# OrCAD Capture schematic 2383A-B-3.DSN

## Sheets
1 PAGE3: size A
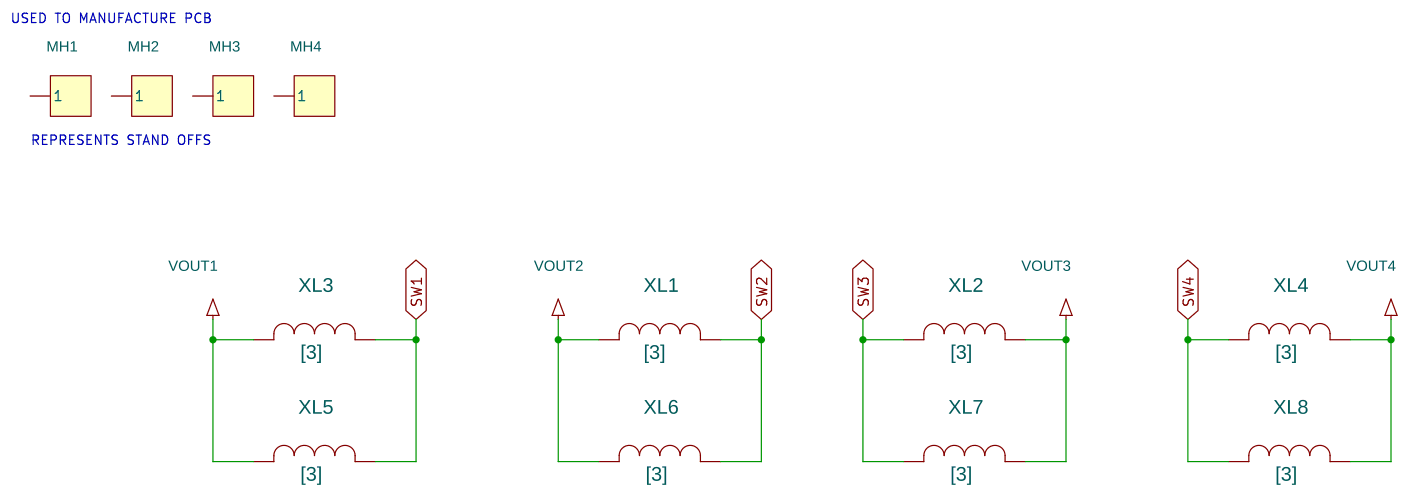
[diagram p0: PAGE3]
2 PAGE1: size Custom
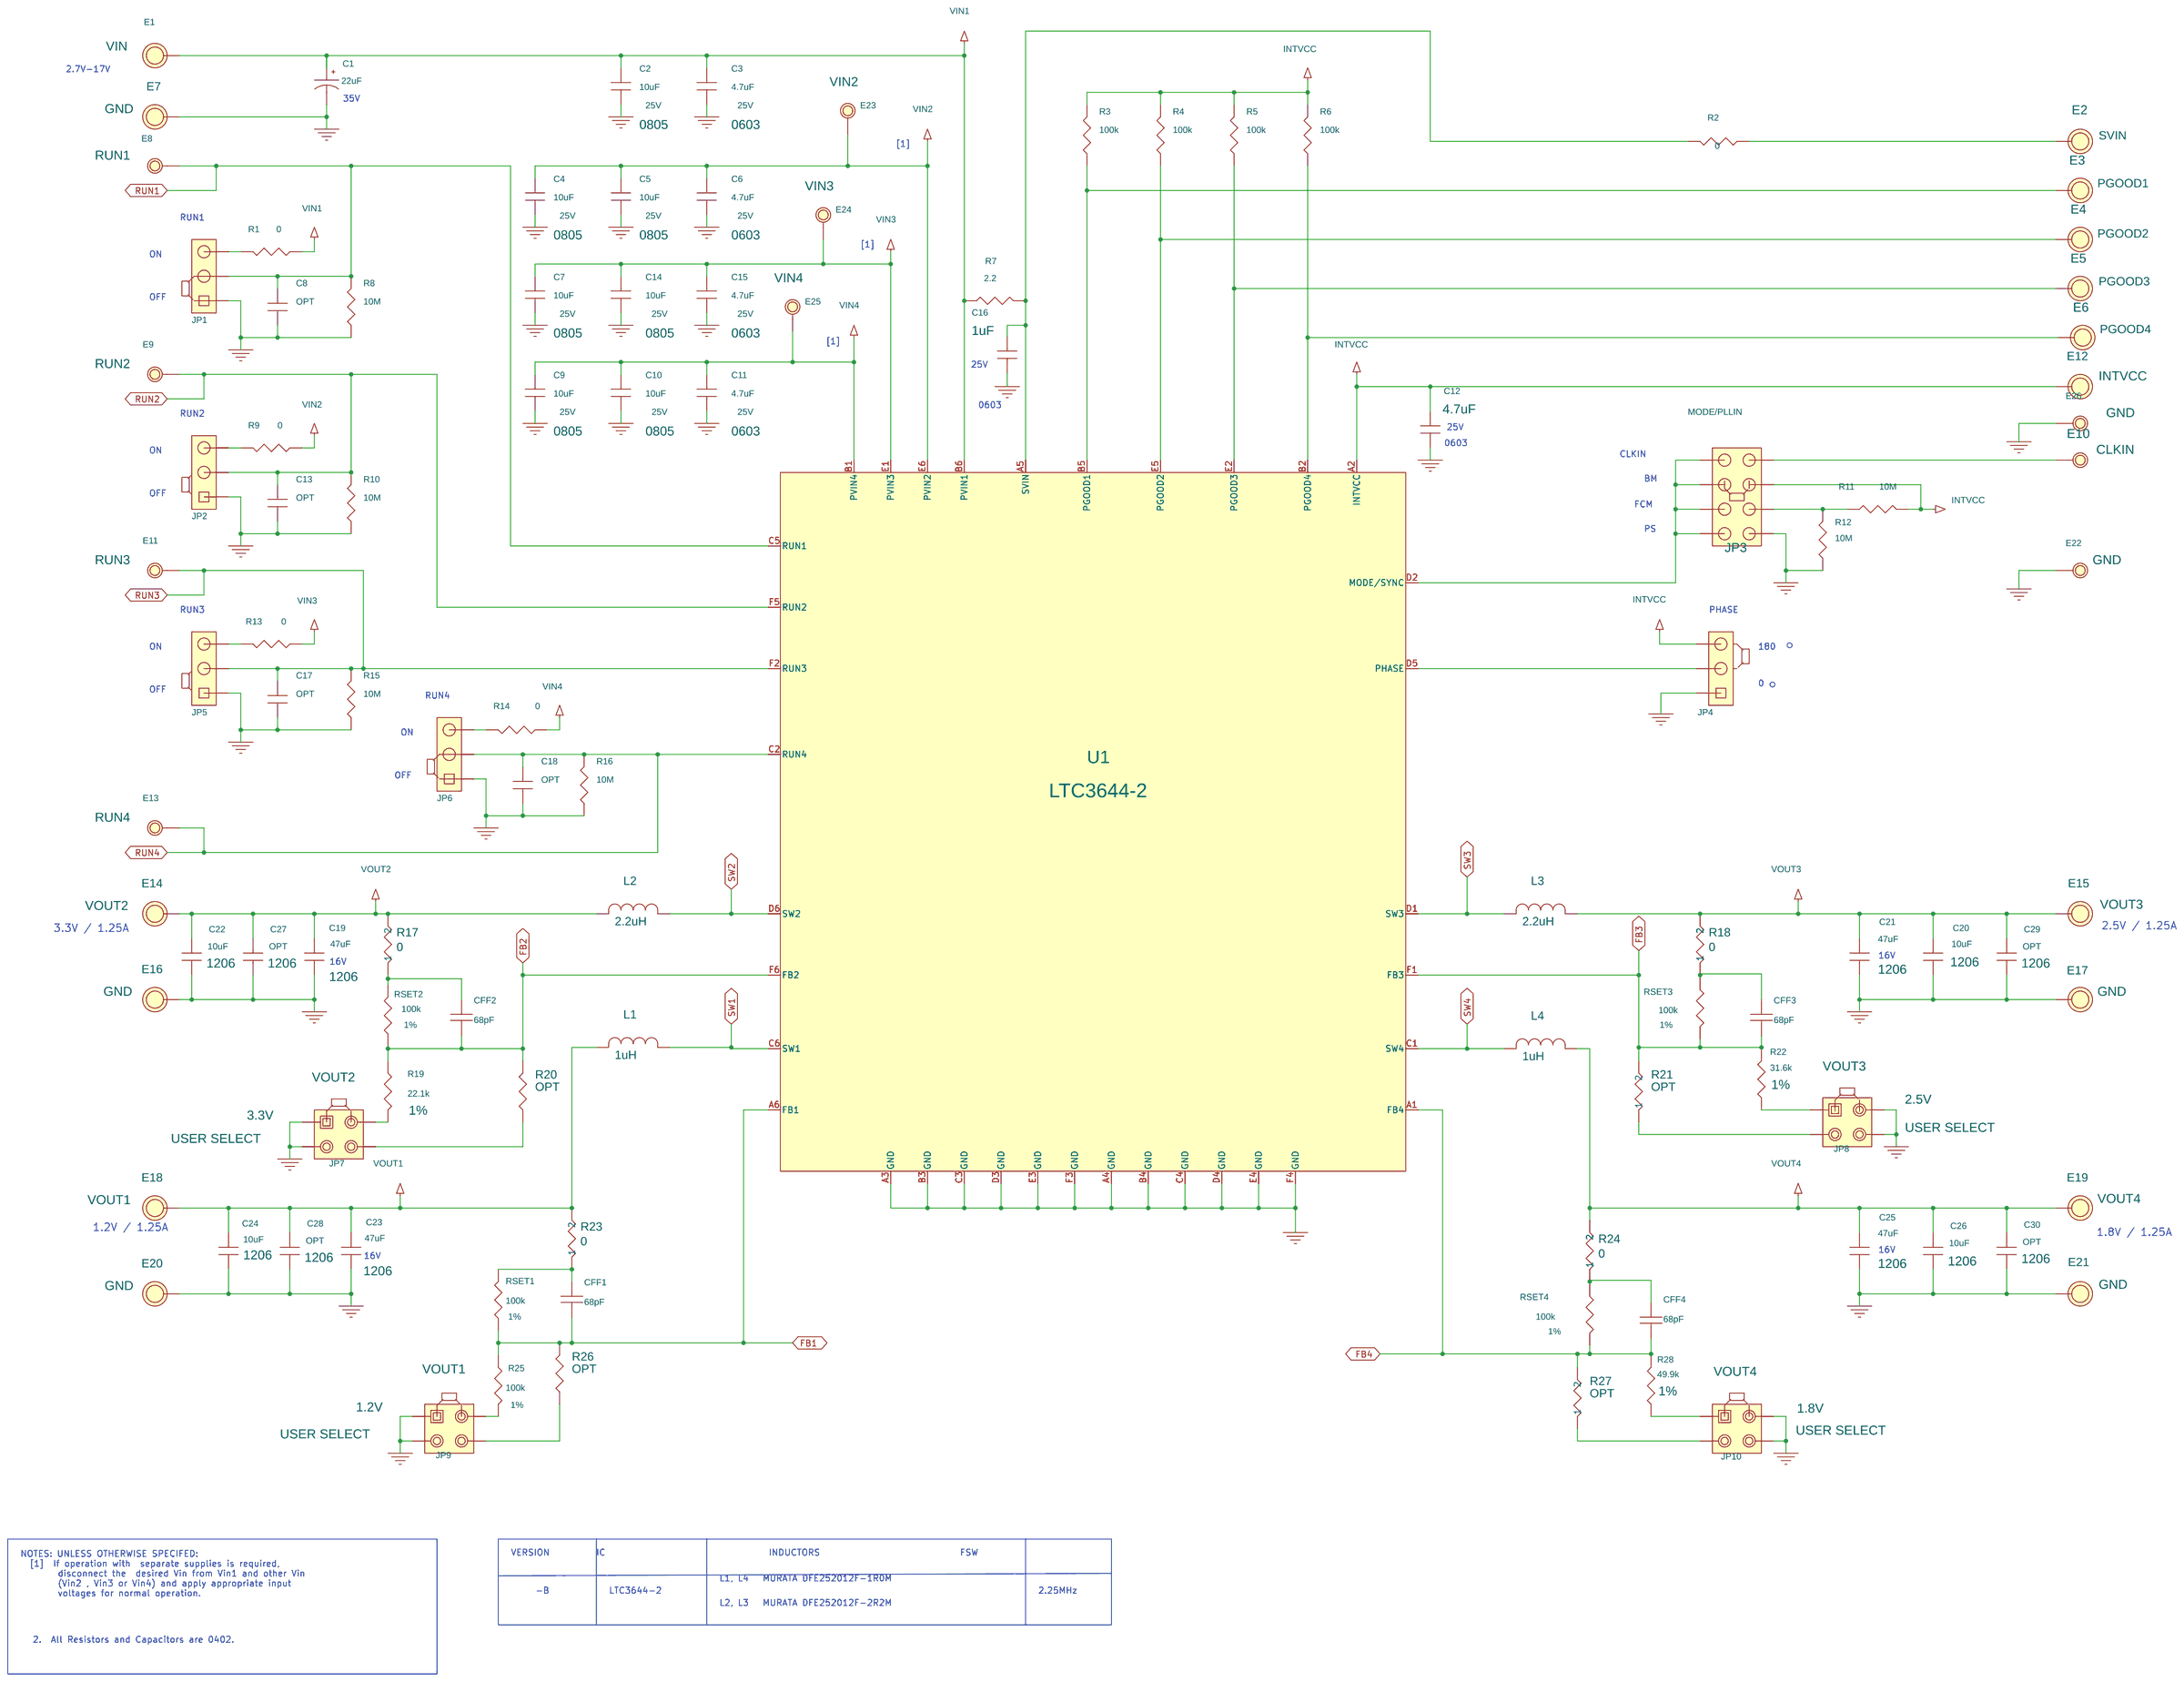
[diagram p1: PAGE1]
3 PAGE2: size Custom; company: ANALOG DEVICES INC.; note: DEMO BOARD BILL OF MATERIALS; note: QUAD 17V, 1.25A SYNCHRONOUS STEP-DOWN REGULATOR
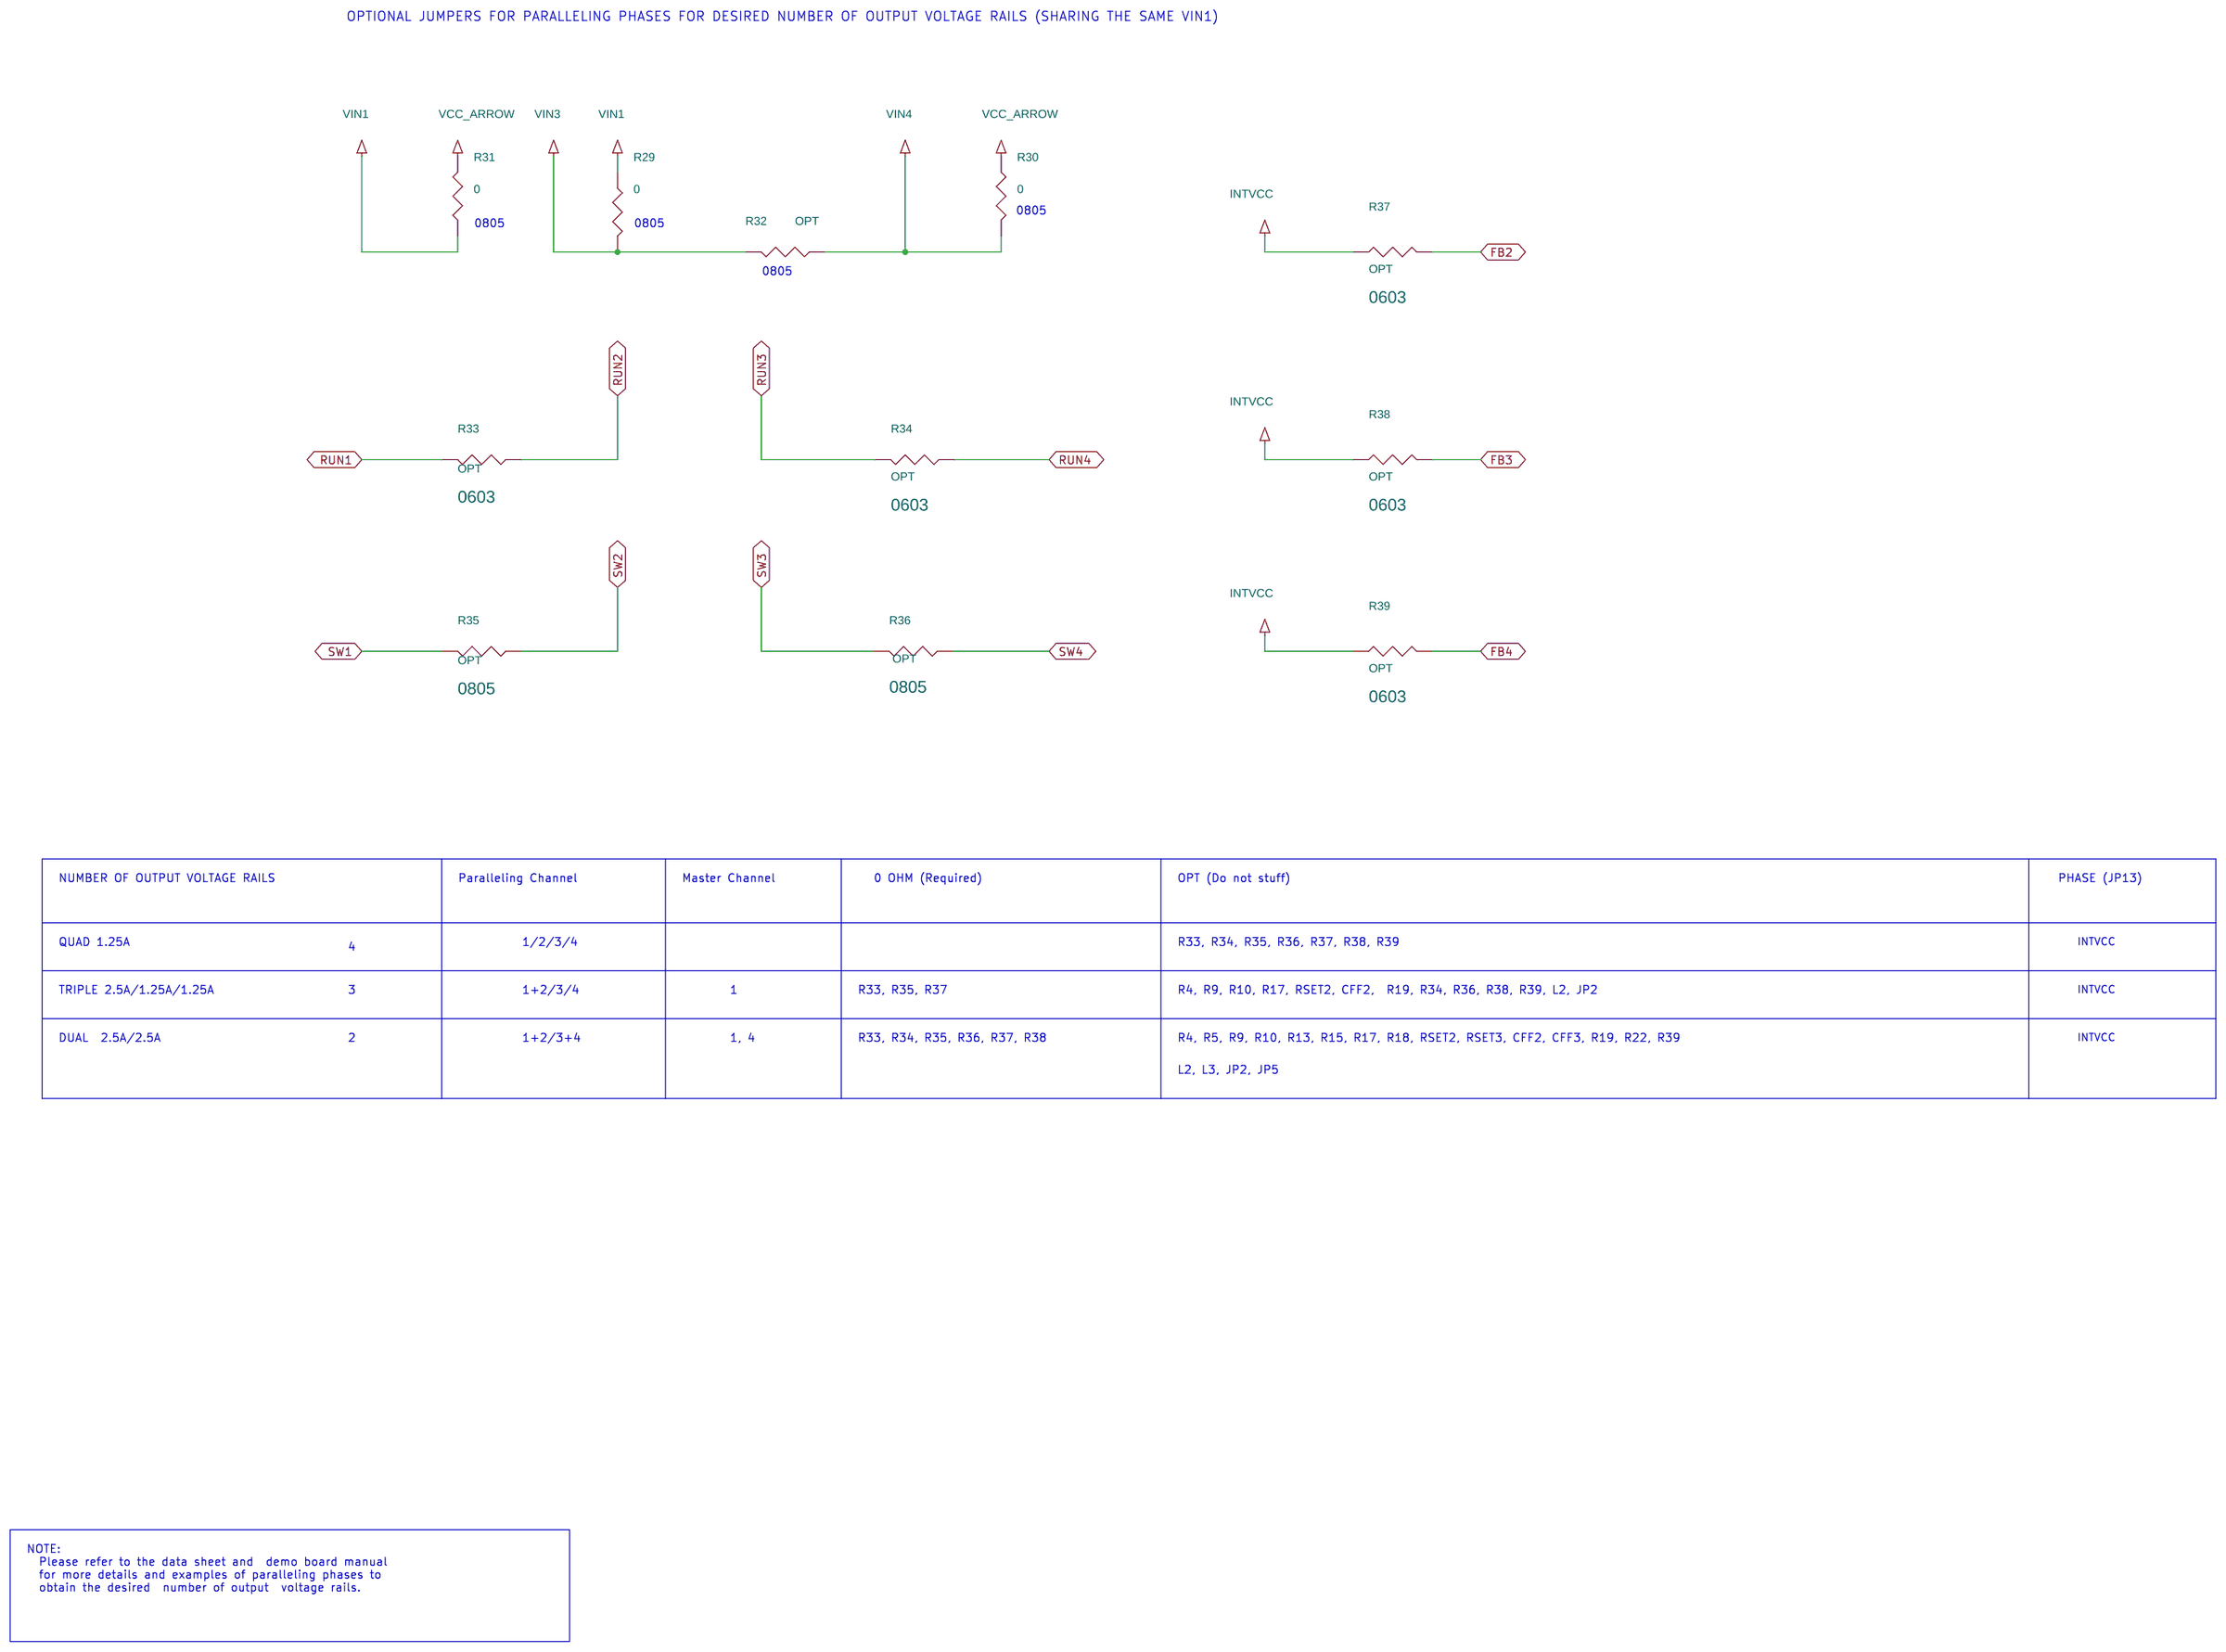
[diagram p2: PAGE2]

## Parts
sheet PAGE1
C1  22uF  [7343]
C2  10uF  [0805]
C3  4.7uF  [0603]
C4  10uF  [0805]
C5  10uF  [0805]
C6  4.7uF  [0603]
C7  10uF  [0805]
C8  OPT  [0402]
C9  10uF  [0805]
C10  10uF  [0805]
C11  4.7uF  [0603]
C12  4.7uF  [0603]
C13  OPT  [0402]
C14  10uF  [0805]
C15  4.7uF  [0603]
C16  1uF  [0603]
C17  OPT  [0402]
C18  OPT  [0402]
C19  47uF  [1206]
C20  10uF  [1206]
C21  47uF  [1206]
C22  10uF  [1206]
C23  47uF  [1206]
C24  10uF  [1206]
C25  47uF  [1206]
C26  10uF  [1206]
C27  OPT  [1206]
C28  OPT  [1206]
C29  OPT  [1206]
C30  OPT  [1206]
CFF1  68pF  [CC0402N]
CFF2  68pF  [CC0402N]
CFF3  68pF  [CC0402N]
CFF4  68pF  [CC0402N]
E1  3A  [TP\MMX\2501-2]
E2  E_4  [TP\MMX\2501-2]
E3  E_4  [TP\MMX\2501-2]
E4  E_4  [TP\MMX\2501-2]
E5  E_4  [TP\MMX\2501-2]
E6  E_4  [TP\MMX\2501-2]
E7  0  [TP\MMX\2501-2]
E8  RUN1  [TP\MMX\2308-2]
E9  RUN2  [TP\MMX\2308-2]
E10  CLKIN  [TP\MMX\2308-2]
E11  RUN3  [TP\MMX\2308-2]
E12  E_4  [TP\MMX\2501-2]
E13  RUN4  [TP\MMX\2308-2]
E14  2.7V - 17V  [TP\MMX\2501-2]
E15  E_4  [TP\MMX\2501-2]
E16  0  [TP\MMX\2501-2]
E17  0  [TP\MMX\2501-2]
E18  E_4  [TP\MMX\2501-2]
E19  3.6V  [TP\MMX\2501-2]
E20  0  [TP\MMX\2501-2]
E21  0  [TP\MMX\2501-2]
E22  GND  [TP\MMX\2308-2]
E23  VIN2  [TP\MMX\2308-2]
E24  VIN3  [TP\MMX\2308-2]
E25  VIN4  [TP\MMX\2308-2]
E26  GND  [TP\MMX\2308-2]
JP1  3 Pins 2mm Ctrs.  [HD1X3-079]
JP2  3 Pins 2mm Ctrs.  [HD1X3-079]
JP3  3 Pins 2mm Ctrs.  [HDR2X4_2MM]
JP4  3 Pins 2mm Ctrs.  [HD1X3-079]
JP5  3 Pins 2mm Ctrs.  [HD1X3-079]
JP6  3 Pins 2mm Ctrs.  [HD1X3-079]
JP7  2 Pins 2mm Ctrs.  [HDR\2X2\2MM]
JP8  2 Pins 2mm Ctrs.  [HDR\2X2\2MM]
JP9  2 Pins 2mm Ctrs.  [HDR\2X2\2MM]
JP10  2 Pins 2mm Ctrs.  [HDR\2X2\2MM]
L1  1uH  [IND\CLCRFT\XFL4020]
L2  2.2uH  [IND\CLCRFT\XFL4020]
L3  2.2uH  [IND\CLCRFT\XFL4020]
L4  1uH  [IND\CLCRFT\XFL4020]
R1  0  [0402]
R2  0  [0402]
R3  100k  [0402]
R4  100k  [0402]
R5  100k  [0402]
R6  100k  [0402]
R7  2.2  [0402]
R8  10M  [0402]
R9  0  [0402]
R10  10M  [0402]
R11  10M  [0402]
R12  10M  [0402]
R13  0  [0402]
R14  0  [0402]
R15  10M  [0402]
R16  10M  [0402]
R17  0  [0402]
R18  0  [0402]
R19  22.1k  [CR0402N]
R20  OPT  [0402]
R21  OPT  [0402]
R22  31.6k  [CR0402N]
R23  0  [0402]
R24  0  [0402]
R25  100k  [CR0402N]
R26  OPT  [0402]
R27  OPT  [0402]
R28  49.9k  [CR0402N]
RSET1  100k  [CR0402N]
RSET2  100k  [CR0402N]
RSET3  100k  [CR0402N]
RSET4  100k  [CR0402N]
U1  LTC3644-2  [LT_BGA-36_5X5]
XJP1  2mm Ctrs.
XJP2  2mm Ctrs.
XJP3  2mm Ctrs.
XJP4  2mm Ctrs.
XJP5  2mm Ctrs.
XJP6  2mm Ctrs.
XJP7  2mm Ctrs.
XJP8  2mm Ctrs.
XJP9  2mm Ctrs.
XJP10  2mm Ctrs.
sheet PAGE2
R29  0  [0805]
R30  0  [0805]
R31  0  [0805]
R32  OPT  [0805]
R33  OPT  [0603]
R34  OPT  [0603]
R35  OPT  [0805]
R36  OPT  [0805]
R37  OPT  [0603]
R38  OPT  [0603]
R39  OPT  [0603]
sheet PAGE3
MH1  CON1  [KEYSTONE_8831]
MH2  CON1  [KEYSTONE_8831]
MH3  CON1  [KEYSTONE_8831]
MH4  CON1  [KEYSTONE_8831]
XL1  [3]  [IND\TOKO\FDSD0312]
XL2  [3]  [IND\TOKO\FDSD0312]
XL3  [3]  [IND\TOKO\FDSD0312]
XL4  [3]  [IND\TOKO\FDSD0312]
XL5  [3]  [IND\CLCRFT_XAL5030-801]
XL6  [3]  [IND\CLCRFT_XAL5030-801]
XL7  [3]  [IND\CLCRFT_XAL5030-801]
XL8  [3]  [IND\CLCRFT_XAL5030-801]

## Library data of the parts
C1 = CAP_POL: CAP. 2917 22uF 20% 35V TANT; Part Number: AVX TPSE226M035R0125
C2 C4 C5 C7 C9 C10 C14 = CAP1210: CAP, 0805 10uF 10% 25V X5R; 1ST PART FIELD: 25V; 2ND PART FIELD: 1210-3743; Part Number: MURATA GRM21BR61E106KA73L
C3 C6 C11 C15 = CAP1210: CAP, 0603 4.7uF 20% 25V X5R; 1ST PART FIELD: 25V; 2ND PART FIELD: 1210-3743; Part Number: MURATA GRM188R61E475ME11D
C8 C13 C17 C18 = CAP1206: CAP, 0402 OPTION; 1ST PART FIELD: 25V; 2ND PART FIELD: 0805-1206; Part Number: OPTION
C12 = CAP1206: CAP, 0603 4.7uF 20% 25V X5R; 1ST PART FIELD: 25V; 2ND PART FIELD: 0805-1206; Part Number: MURATA GRM188R61E475ME11D
C16 = CAP1206: CAP, 0603 1uF 10% 25V X7R; 1ST PART FIELD: 25V; 2ND PART FIELD: 0805-1206; Part Number: MURATA GRM188R71E105KA12D
C19 C21 C23 C25 = CAP1206: CAP, 1206 47uF 10% 16V X5R; 1ST PART FIELD: 16V; Part Number: MURATA GRM31CR61C476ME44L
C20 C22 C24 C26 = CAP1206: CAP, 1206 10uF 10% 16V X7R; 1ST PART FIELD: 25V; 2ND PART FIELD: 0805-1206; Part Number: TDK C3216X7R1C106K160AC
C27-C30 = CAP1206: CAP, 1206 OPTION; 1ST PART FIELD: 25V; 2ND PART FIELD: 0805-1206; Part Number: OPTION
CFF1-CFF4 = CAP: CAP.,68pF,C0G,50V,5%,0402; CLASS: DISCRETE; Dielectric Type: C0G; FPLIST: CC0402N,CC0402L,CC0402M; Inventory Qty: 0; Manufacturer: AVX; Manufacturer PN: 04025A680JAT2A; PART_NUMBER: 150-0084; Package Size: 0402; Rated Voltage: 50V; Tolerance: 5%
E1 = E_4: TURRET; INPUT: VIN; Part Number: MILL-MAX 2501-2-00-80-00-00-07-0; STATUS: 1.6V, 1.8V, 2.0V OR 2.5V @ 15A
E2 = E_4: TURRET; INPUT: SVIN; Part Number: MILL-MAX 2501-2-00-80-00-00-07-0
E3 = E_4: TURRET; INPUT: PGOOD1; Part Number: MILL-MAX 2501-2-00-80-00-00-07-0
E4 = E_4: TURRET; INPUT: PGOOD2; Part Number: MILL-MAX 2501-2-00-80-00-00-07-0
E5 = E_4: TURRET; INPUT: PGOOD3; Part Number: MILL-MAX 2501-2-00-80-00-00-07-0
E6 = E_4: TURRET; INPUT: PGOOD4; Part Number: MILL-MAX 2501-2-00-80-00-00-07-0
E7 E16 E17 E20 E21 = E_4: TURRET; INPUT: GND; Part Number: MILL-MAX 2501-2-00-80-00-00-07-0
E8-E11 E13 E22-E26 = MillMax-2501: TURRET; Part Number: MILL-MAX 2308-2-00-80-00-00-07-0
E12 = E_4: TURRET; INPUT: INTVCC; Part Number: MILL-MAX 2501-2-00-80-00-00-07-0
E14 = E_4: TURRET; INPUT: VOUT2; Part Number: MILL-MAX 2501-2-00-80-00-00-07-0; STATUS: 1.6V, 1.8V, 2.0V OR 2.5V @ 15A
E15 = E_4: TURRET; INPUT: VOUT3; Part Number: MILL-MAX 2501-2-00-80-00-00-07-0
E18 = E_4: TURRET; INPUT: VOUT1; Part Number: MILL-MAX 2501-2-00-80-00-00-07-0; STATUS: 1
E19 = E_4: TURRET; INPUT: VOUT4; Part Number: MILL-MAX 2501-2-00-80-00-00-07-0
JP1 JP2 JP4-JP6 = Commcon2802s03g2_7: HEADER, 3PIN, 2mm; 11th Part Field: SOFT-START; 12th Part Field: TRACK; 9th Part Field: ON; Part Number: WURTH ELEKTRONIK 62000311121
JP3 = Commcon2802s03g2_13: HEADER, 2X4PINS  2mm; 10th Part Field: 10th??; 11th Part Field: VOUT1; 12th Part Field: MODE/PLLIN; Part Number: WURTH ELEKTRONIK 62000821121
JP7 = JP4: HEADER, 2PIN, DBL ROW 2mm; 4th Part Field: USER SELECT; 5th Part Field: 3.3V; 7th Part Field: GND; 9th Part Field: VOUT2; Part Number: WURTH ELEKTRONIK 62000421121
JP8 = JP4: HEADER, 2PIN, DBL ROW 2mm; 4th Part Field: 2.5V; 5th Part Field: USER SELECT; 7th Part Field: GND; 9th Part Field: VOUT3; Part Number: WURTH ELEKTRONIK 62000421121
JP9 = JP4: HEADER, 2PIN, DBL ROW 2mm; 4th Part Field: 1.2V; 5th Part Field: USER SELECT; 7th Part Field: GND; 9th Part Field: VOUT1; Part Number: WURTH ELEKTRONIK 62000421121
JP10 = JP4: HEADER, 2PIN, DBL ROW 2mm; 4th Part Field: 1.8V; 5th Part Field: USER SELECT; 7th Part Field: GND; 9th Part Field: VOUT4; Part Number: WURTH ELEKTRONIK 62000421121
L1 L4 = D53LC: IND, 1uH; Part Number: MURATA DFE252012F-1R0M
L2 L3 = D53LC: IND, 2.2uH; Part Number: MURATA DFE252012F-2R2M
R1 R2 R9 R13 R14 = AAC-0603: RES, 0402 0 OHM JUMPER; Part Number: VISHAY CRCW04020000Z0ED
R3-R6 = AAC-0603: RES, 0402 100k OHMS 1% 0.63W; Part Number: VISHAY CRCW0402100KFKED
R7 = AAC-0603: RES, 0402 2.2 OHMS 1% 0.63W; Part Number: VISHAY CRCW04022R20FNED
R8 R10-R12 R15 R16 = AAC-0603: RES, 0402 10M OHMS 1% 0.63W; Part Number: VISHAY CRCW040210M0FKED
R17 = R: RES, 0402 0 OHM JUMPER; 5%: 1%; Part Number: VISHAY CRCW04020000Z0ED
R18 = R_5: RES, 0402 0 OHM JUMPER; 5%: 1%; Part Number: VISHAY CRCW04020000Z0ED
R19 = RES: RES, 0402 22.1K OHMS,1%,0.63W; CLASS: DISCRETE; FPLIST: CR0402N,CR0402L,CR0402M; Inventory Qty: 20000; Manufacturer: Vishay; Manufacturer PN: CRCW040222K1FKED; PART_NUMBER: 100-1388; Package Size: 0402; Part Number: VISHAY CRCW040222K1FKED; Rated Power: 1/16W; Temperature Coefficient: +/-100PPM; Tolerance: 1%
R20 R26 = RESISTOR: RES, 0402 OPTION; Part Number: OPTION; Tolerance: 1%
R21 = R_2: RES, 0402 OPTION; 5%: 1%; Part Number: OPTION; Tolerance: 1%
R22 = RES: RES.,31.6k OHMS,1%,1/16W,0402,AEC-Q200; CLASS: DISCRETE; FPLIST: CR0402N,CR0402L,CR0402M; Inventory Qty: 29500; Manufacturer: STACKPOLE ELECTRONICS, INC.; Manufacturer PN: RMCF0402FT31K6; PART_NUMBER: 100-0353; Package Size: 0402; Part Number: STACKPOLE ELECTRONICS, INC. RMCF0402FT31K6; Rated Power: 1/16W; Temperature Coefficient: 100ppm/C; Tolerance: 1%
R23 = R_3: RES, 0402 0 OHM JUMPER; 5%: 1%; Part Number: VISHAY CRCW04020000Z0ED
R24 = R_1: RES, 0402 0 OHM JUMPER; 5%: 1%; Part Number: VISHAY CRCW04020000Z0ED
R25 RSET1-RSET4 = RES: RES.,100k OHMS,1%,1/10W,0402,AEC-Q200; CLASS: DISCRETE; FPLIST: CR0402N,CR0402L,CR0402M; Inventory Qty: 27556; Manufacturer: PANASONIC; Manufacturer PN: ERJ2RKF1003X; PART_NUMBER: 100-2089; Package Size: 0402; Part Number: PANASONIC ERJ2RKF1003X; Rated Power: 1/10W; Temperature Coefficient: 100ppm/C; Tolerance: 1%
R27 = R_4: RES, 0402 OPTION; 5%: 1%; Part Number: OPTION; Tolerance: 1%
R28 = RES: RES.,49.9k OHMS,1%,1/10W,0402,AEC-Q200; CLASS: DISCRETE; FPLIST: CR0402N,CR0402L,CR0402M; Inventory Qty: 39803; Manufacturer: KOA SPEER; Manufacturer PN: RK73H1ETTP4992F; PART_NUMBER: 100-0097; Package Size: 0402; Part Number: KOA SPEER RK73H1ETTP4992F; Rated Power: 1/10W; Temperature Coefficient: 100ppm/C; Tolerance: 1%
U1 = LTM4642EY_27: IC, QUAD 17V, 1A SYNCHRONOUS STEP-DOWN REGULATOR; Part Number: LINEAR TECH. LTC3644-2BGA
XJP1 XJP2 XJP4-XJP6 = CommconCCIJ2MM-138G: SHUNT, 2mm; Part Number: WURTH ELEKTRONIK 60800213421
XJP3 = CommconCCIJ2MM-138G_0: SHUNT, 2mm; Part Number: WURTH ELEKTRONIK 60800213421
XJP7-XJP10 = Samtec_2SN-BK-G: SHUNT, 2mm; Part Number: WURTH ELEKTRONIK 60800213421
R29-R31 = AAC-0603: RES, 0805 0 OHM JUMPER; Part Number: VISHAY CRCW08050000Z0EA
R32 = AAC-0603: RES, 1206 OPTION; Part Number: OPTION
R33 R34 = AAC-0603: RES, 0603 OPTION; Part Number: OPTION
R35 R36 = AAC-0603: RES, 0805 OPTION; Part Number: OPTION
R37-R39 = RESISTOR: RES, 0603 OPTION; Part Number: OPTION
MH1-MH4 = CON1: STANDOFF, SNAP ON 12.7mm; Part Number: WURTH ELEKTRONIK 702935000
XL1-XL8 = D53LC: FOOT PRINT; Part Number: FOOT PRINT

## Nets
GND: C1.2 C2.2 C3.2 C4.2 C5.2 C6.2 C7.2 C8.2 C9.2 C10.2 C11.2 C12.2 C13.2 C14.2 C15.2 C16.1 C17.2 C18.2 C19.1 C20.2 C21.2 C22.1 C23.1 C24.1 C25.2 C26.2 C27.1 C28.1 C29.1 C30.1 E7.1(A) E16.1(A) E17.1(A) E20.1(A) E21.1(A) E22.1 E26.1 JP1.1 JP2.1 JP3.8 JP4.1 JP5.1 JP6.1 JP7.1 JP7.3 JP8.2 JP8.4 JP9.1 JP9.3 JP10.2 JP10.4 R8.1 R10.1 R12.1 R15.1 R16.1 U1.A3(GND) U1.A4(GND) U1.B3(GND) U1.B4(GND) U1.C3(GND) U1.C4(GND) U1.D3(GND) U1.D4(GND) U1.E3(GND) U1.E4(GND) U1.F3(GND) U1.F4(GND)
VIN1: C1.1 C2.1 C3.1 E1.1(A) R1.2 R7.1 R29.1 R30.1 R31.1 U1.B6(PVIN1)
VIN2: C4.1 C5.1 C6.1 E23.1 R9.2 R31.2 U1.E6(PVIN2)
VIN3: C7.1 C14.1 C15.1 E24.1 R13.2 R29.2 R32.2 U1.E1(PVIN3)
VIN4: C9.1 C10.1 C11.1 E25.1 R14.2 R30.2 R32.1 U1.B1(PVIN4)
FB1: CFF1.2 R25.2 R26.2 RSET1.1 U1.A6(FB1)
FB2: CFF2.2 R19.2 R20.2 R37.2 RSET2.1 U1.F6(FB2)
FB3: CFF3.2 R21.2 R22.2 R38.2 RSET3.1 U1.F1(FB3)
FB4: CFF4.2 R27.2 R28.2 R39.2 RSET4.1 U1.A1(FB4)
INTVCC: C12.1 E12.1(A) JP3.4 JP4.3 R3.2 R4.2 R5.2 R6.2 R11.2 R37.1 R38.1 R39.1 U1.A2(INTVCC)
RUN1: C8.1 E8.1 JP1.2 R8.2 R33.2 U1.C5(RUN1)
RUN2: C13.1 E9.1 JP2.2 R10.2 R33.1 U1.F5(RUN2)
RUN3: C17.1 E11.1 JP5.2 R15.2 R34.2 U1.F2(RUN3)
RUN4: C18.1 E13.1 JP6.2 R16.2 R34.1 U1.C2(RUN4)
SW1: L1.2 R35.2 U1.C6(SW1) XL3.2 XL5.2
SW2: L2.2 R35.1 U1.D6(SW2) XL1.2 XL6.2
SW3: L3.1 R36.2 U1.D1(SW3) XL2.1 XL7.1
SW4: L4.1 R36.1 U1.C1(SW4) XL4.1 XL8.1
VOUT1: C23.2 C24.2 C28.2 E18.1(A) L1.1 R23.2 XL3.1 XL5.1
VOUT2: C19.2 C22.2 C27.2 E14.1(A) L2.1 R17.2 XL1.1 XL6.1
VOUT3: C20.1 C21.1 C29.2 E15.1(A) L3.2 R18.2 XL2.2 XL7.2
VOUT4: C25.1 C26.1 C30.2 E19.1(A) L4.2 R24.2 XL4.2 XL8.2
N19617800: E3.1(A) R3.1 U1.B5(PGOOD1)
N19617816: E4.1(A) R4.1 U1.E5(PGOOD2)
N19618300: E6.1(A) R6.1 U1.B2(PGOOD4)
N19630406: JP1.3 R1.1
N19646419: C16.2 R2.1 R7.2 U1.A5(SVIN)
N19659099: JP3.1 JP3.3 JP3.5 JP3.7 U1.D2(MODE/SYNC)
N19660260: JP3.6 R11.1 R12.2
N19662265: E10.1 JP3.2
N19662372: JP4.2 U1.D5(PHASE)
N19664351: CFF3.1 R18.1 RSET3.2
N19664868: CFF4.1 R24.1 RSET4.2
N19669710: CFF1.1 R23.1 RSET1.2
N19670620: CFF2.1 R17.1 RSET2.2
N19773332: JP2.3 R9.1
N19774216: JP5.3 R13.1
N19774701: JP6.3 R14.1
N19779287: E5.1(A) R5.1 U1.E2(PGOOD3)
N19781053: E2.1(A) R2.2
N19787386: JP7.4 R20.1
N19788454: JP7.2 R19.1
N19789198: JP9.2 R25.1
N19789204: JP9.4 R26.1
N19791646: JP8.1 R22.1
N19791650: JP8.3 R21.1
N19792862: JP10.1 R28.1
N19793677: JP10.3 R27.1

Not connected (* = marked no-connect by the designer): MH1 1; MH2 1; MH3 1; MH4 1

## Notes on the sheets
sheet 1
- USED TO MANUFACTURE PCB
- REPRESENTS STAND OFFS
sheet 2
- 2.7V-17V
- 35V
- [1]
- RUN1
- [1]
- ON
- OFF
- [1]
- 25V
- 0603
- RUN2
- 25V
- 0603
- ON
- CLKIN
- BM
- OFF
- FCM
- PS
- RUN3
- PHASE
- ON
- 180
- OFF
- RUN4
- 0
- ON
- OFF
- 3.3V / 1.25A
- 2.5V / 1.25A
- 16V
- 16V
- 1.2V / 1.25A
- 1.8V / 1.25A
- 16V
- 16V
- NOTES: UNLESS OTHERWISE SPECIFED:
    [1]  If operation with  separate supplies is required,
          disconnect the  desired Vin from Vin1 and other Vin
          (Vin2 , Vin3 or Vin4) and apply appropriate input
          voltages for normal operation.
- VERSION          IC                                   INDUCTORS                              FSW
- L1, L4   MURATA DFE252012F-1R0M
- -B
- LTC3644-2
- 2.25MHz
- L2, L3   MURATA DFE252012F-2R2M
- 2.  All Resistors and Capacitors are 0402.
sheet 3
- OPTIONAL JUMPERS FOR PARALLELING PHASES FOR DESIRED NUMBER OF OUTPUT VOLTAGE RAILS (SHARING THE SAME VIN1)
- 0805
- 0805
- 0805
- 0805
- NUMBER OF OUTPUT VOLTAGE RAILS
- Paralleling Channel
- Master Channel
- 0 OHM (Required)
- OPT (Do not stuff)
- PHASE (JP13)
- QUAD 1.25A
- 4
- 1/2/3/4
- R33, R34, R35, R36, R37, R38, R39
- INTVCC
- TRIPLE 2.5A/1.25A/1.25A
- 3
- 1+2/3/4
- 1
- R33, R35, R37
- R4, R9, R10, R17, RSET2, CFF2,  R19, R34, R36, R38, R39, L2, JP2
- INTVCC
- DUAL  2.5A/2.5A
- 2
- 1+2/3+4
- 1, 4
- R33, R34, R35, R36, R37, R38
- R4, R5, R9, R10, R13, R15, R17, R18, RSET2, RSET3, CFF2, CFF3, R19, R22, R39
- INTVCC
- L2, L3, JP2, JP5
- NOTE:
    Please refer to the data sheet and  demo board manual
    for more details and examples of paralleling phases to
    obtain the desired  number of output  voltage rails.
